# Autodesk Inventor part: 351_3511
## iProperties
Author: tomm
Created: 2002-01
Part Number: 351_3511
Document SubType Name: Sheet Metal
Designer: tomm
Material: Steel, Mild
Control State: 0
Master: False
Checked Out: False
Last Check In Date: 2002-01-29
PropertySet Name: Design Tracking Control
Last Check In By: tomm
Shininess: 70.0
PropertySet Name: _Private Model Information
Density: 7.86
Volume: 2.629480045343953
Area: 27.45875303893604
PropertySet Name: Model Information
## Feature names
1. Base1
2. Bend1
3. Corner Round1
4. Corner Round2
